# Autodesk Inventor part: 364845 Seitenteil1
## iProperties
Company: Hundt & Weber AG Schaltgeräte
Created: 2010-11
Part Number: 364845 Seitenteil1
Material: 1.0120
Document SubType Name: Modeling
Designer: I.Baliuc
Manufacturer: Standard
Standards Organization: Custom
Description: Seitenteil, Trenner
Cost Center: 5,196 kg
Authority: 661896 mm^3
Density: 7.85 g/cm^3
HalbzeugNorm: DIN 174
Zweck: HSLT / HSE - Standardseite
Abmessung: Fl. 120x12-170
SaveDate: 2006-10-28
SaveTime: 20:23
TotalMass: 5,196 kg
TotalVolume: 661896 mm^3
Author: AHausen
Revision Number: 364845
Keywords: 380125
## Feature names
1. Extrusion2
2. Bohrung_Ø13 [Hole]
3. Bohrung2 [Hole]
4. Bohrung3 [Hole]
5. Bohrung_M8_01 [Hole]
6. Bohrung_M8_02 [Hole]
7. Bohrung_M6 [Hole]
8. Bohrung_M5 [Hole]
9. Neue Bohrung (zusätzlich) [Rectangular Pattern]
